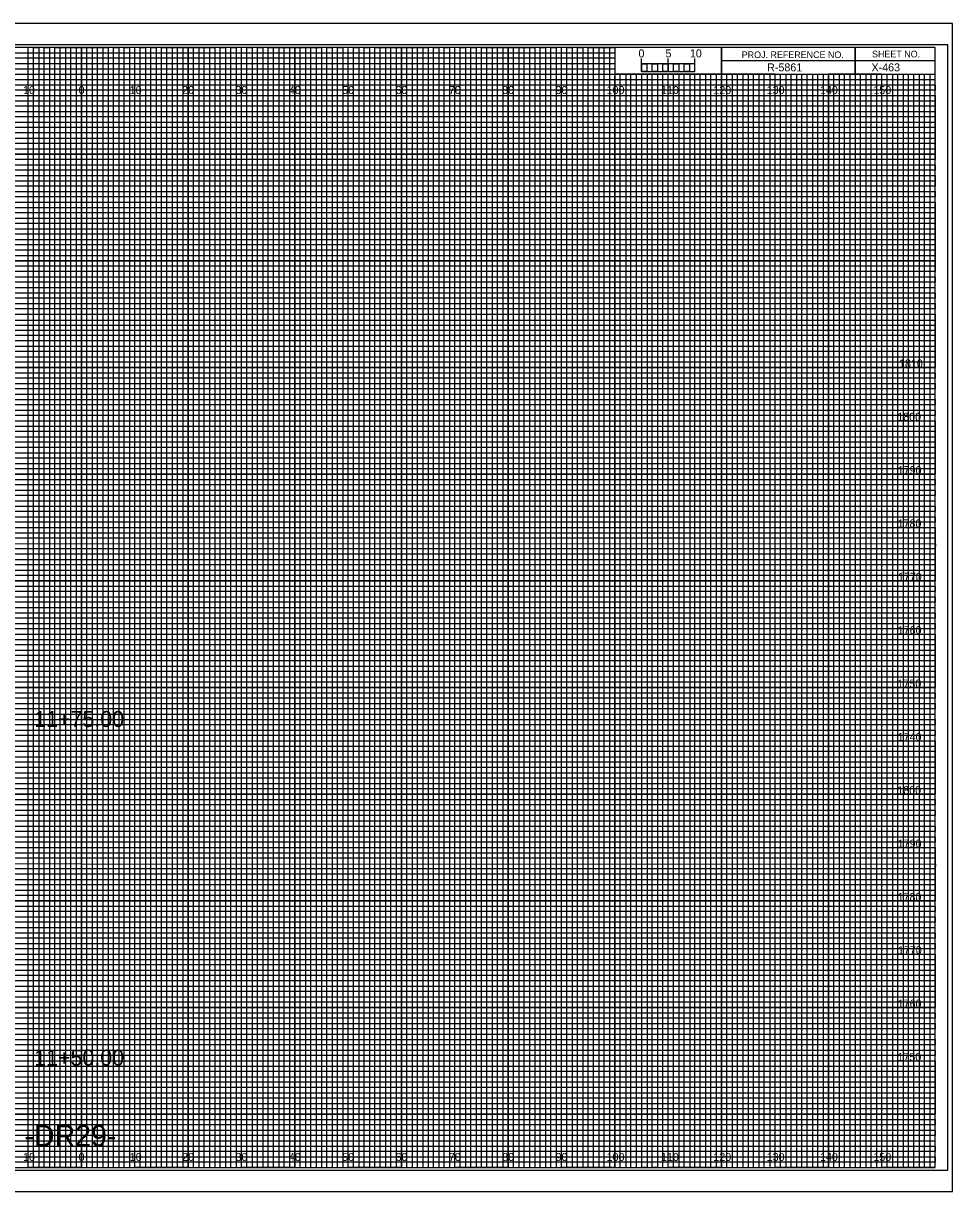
# Model space of a CAD drawing. Extents: x -13 to 323, y -5 to 874.
# Drawn here: x 149.1 to 323.3, y 435.5 to 654.5 of the extents above; entities that cross this region are included whole.
import ezdxf

# ---------------------------------------------------------------- set-up
doc = ezdxf.new("R2010")
doc.units = 0
for name, color, linetype in [('Prop Horizontal Alignment', 7, 'Continuous'), ('Prop XS Alignment Label', 7, 'Continuous'), ('Prop XS Bar Scale Labels', 7, 'Continuous'), ('Prop XS DDE', 7, 'Continuous'), ('Prop XS DDE Elevations', 7, 'Continuous'), ('Prop XS DDE Slope Text', 7, 'Continuous'), ('Prop XS Gore Control Minimum', 7, 'Continuous'), ('Prop XS Project Number', 7, 'Continuous'), ('Prop XS Sheet Number', 7, 'Continuous'), ('Prop XS Shoulder Borrow Shape', 7, 'Continuous'), ('Raster_Level_0', 7, 'Continuous'), ('Scratch_Level_3', 7, 'Continuous'), ('Sheet Cross Section Scale CELL', 7, 'Continuous'), ('Sheet Cutting Line CELL', 7, 'Continuous'), ('Sheet DOT Grid CELL', 7, 'Continuous'), ('Sheet Plot Border Inside CELL', 7, 'Continuous'), ('Sheet Plot Border Outside CELL', 7, 'Continuous')]:
    doc.layers.add(name, color=color, linetype=linetype)

msp = doc.modelspace()

# ---------------------------------------------------------------- linework, layer by layer
at = {"layer": 'Prop XS DDE'}
for p, q in [((0, 649), (260, 649)), ((260, 649), (260, 647.98)), ((260, 647.98), (0, 647.98)), ((0, 647), (260, 647)), ((260, 647), (260, 645.89)), ((260, 645.89), (0, 645.89)), ((0, 644), (320, 644))]:
    msp.add_line(p, q, dxfattribs=at)
for points in [[(0, 643), (270, 643), (320, 643), (320, 642), (0, 642)], [(0, 641), (320, 641), (320, 639), (0, 639)], [(0, 638), (320, 638), (320, 637), (0, 636.98)], [(0, 636), (320, 636), (320, 634), (0, 634)], [(0, 633), (320, 633), (320, 632), (0, 632)], [(0, 631), (320, 631), (320, 629), (0, 629)], [(0, 628), (320, 628), (320, 627), (0, 627)], [(0, 626), (320, 626), (320, 624), (0, 624)], [(0, 623), (320, 623), (320, 622), (0, 622)], [(0, 621), (320, 621), (320, 619), (0, 619)], [(0, 618), (320, 618), (320, 617), (0, 617)], [(0, 616), (320, 616), (320, 613.95), (320, 613), (320, 612), (0, 612)], [(0, 614), (320, 614), (320, 613), (0, 613)], [(0, 611), (320, 611), (320, 609), (0, 609.03)], [(0, 609.03), (320, 609), (320, 608), (0, 608)], [(0, 607), (320, 607), (320, 606), (0, 606)], [(0, 604), (320, 604), (320, 603), (0, 603)], [(0, 602), (320, 602), (320, 601), (0, 601)], [(-0.07, 598.89), (320, 598.89), (320, 597.88), (-0.07, 597.88)], [(0, 597), (320, 597), (320, 596), (0, 596)], [(0, 594), (320, 594), (320, 593), (0, 593)], [(0, 592), (320, 592), (320, 591), (0, 591)], [(0, 589), (320, 589), (320, 588), (0, 588)], [(0, 587), (320, 587), (320, 586), (0, 586)], [(0, 584), (320, 584), (320, 583), (0, 583)], [(0, 582), (320, 582), (320, 581), (0, 581)], [(0, 579), (320, 579), (319.99, 577.98), (0, 578)], [(0, 577), (320, 577), (320, 576), (0, 576)], [(0, 574), (320, 574), (320, 573), (0, 573)], [(0, 572), (320, 572), (320, 571), (0, 571)], [(0, 569), (320, 569), (320, 568), (0, 568)], [(0, 567), (320, 567), (320, 566), (0, 566)], [(0, 564), (320, 564), (320, 563), (0, 563)], [(0, 562), (320, 562), (320, 561), (0, 561)], [(0, 559), (320, 559), (320, 558), (0, 558)], [(0, 556.99), (320.07, 556.91), (320, 556), (0, 556)], [(0, 554), (320, 554), (320, 553), (0, 553)], [(0, 552), (320, 552), (320, 551), (0, 551)], [(0, 549), (320, 549), (320, 548), (0, 548)], [(0, 547), (320, 547), (320, 546), (0, 546)], [(0, 544), (320, 544), (320, 543), (0, 543)], [(0, 542), (320, 542), (320, 541), (0, 541)], [(0, 539), (320, 539), (320, 538), (0, 538)], [(0, 537), (320, 537), (320, 536), (0, 536)], [(0, 534), (320, 534), (320, 533), (0, 533)], [(0, 532), (320, 532), (320, 531), (0, 531)], [(0, 529), (320, 529), (320, 528), (0, 528)], [(0, 527), (320, 527), (320, 526), (0, 526)], [(0, 524), (320, 524), (320, 523), (0, 523)], [(0, 522), (320, 522), (320, 521), (0, 521)], [(0, 519), (320, 519), (319.99, 517.98), (0, 518)], [(0, 517), (320, 517), (320, 516), (0, 516)], [(0, 514), (320, 514), (320, 513), (0, 513)], [(0, 512), (320, 512), (320, 511), (0, 511)], [(0, 509), (320, 509), (320, 508), (0, 508)], [(0, 507), (320, 507), (320, 506), (0, 506)], [(0, 504), (320, 504), (320, 503), (0, 503)], [(0, 502), (320, 502), (320, 501), (0, 501)], [(0, 499), (320, 499), (320, 498), (0, 498)], [(0, 496.99), (320.07, 496.91), (320, 496), (0, 496)], [(0, 494), (320, 494), (320, 493), (0, 493)], [(0, 492), (320, 492), (320, 491), (0, 491)], [(0, 489), (320, 489), (320, 488), (0, 488)], [(0, 487), (320, 487), (320, 486), (0, 486)], [(0, 484), (320, 484), (320, 483), (0, 483)], [(0, 482), (320, 482), (320, 481), (0, 481)], [(0, 479), (320, 479), (320, 478), (0, 478)], [(0, 477), (320, 477), (320, 476), (0, 476)], [(0, 474), (320, 474), (320, 473), (0, 473)], [(0, 472), (320, 472), (320, 471), (0, 471)], [(0, 469), (320, 469), (320, 468), (0, 468)], [(0, 467), (320, 467), (320, 466), (0, 466)], [(0, 464), (320, 464), (320, 463), (0, 463)], [(0, 462), (320, 462), (320, 461), (0, 461)], [(0, 459), (320, 459), (320, 458), (0, 458)], [(0, 457), (320, 457), (320, 456), (0, 456)], [(0, 454), (320, 454), (320, 453), (0, 453)], [(0, 452), (320, 452), (320, 451), (0, 451)], [(0, 449), (320, 449), (320, 448), (0, 448)], [(0, 447), (320, 447), (320, 446), (0, 446)], [(0, 444), (320, 444), (320, 443), (0, 443)], [(0, 442), (320, 442), (320, 441), (0, 441)]]:
    msp.add_lwpolyline(points, dxfattribs=at)
at = {"layer": 'Prop XS DDE Elevations'}
for p, q in [((267, 645), (266.01, 645)), ((266.01, 645), (266.01, 440)), ((267, 440), (267, 645)), ((269, 645), (268, 645)), ((268, 645), (268, 440)), ((269, 440), (269, 645)), ((266.01, 440), (265, 440)), ((268, 440), (267, 440))]:
    msp.add_line(p, q, dxfattribs=at)
for points in [[(150, 440), (151, 440), (151, 650), (152, 650), (152, 440)], [(152, 440), (153, 440), (153, 650), (154, 650), (154, 440)], [(155, 440), (156, 440), (156, 650), (157, 650), (157, 440)], [(157, 440), (158, 440), (158, 650), (159, 650), (159, 440)], [(160, 440), (161, 440), (161, 650), (162, 650), (162, 440)], [(162, 440), (163, 440), (163, 650), (164, 650), (164, 440)], [(165, 440), (166, 440), (166, 650), (167, 650), (167, 440)], [(167, 440), (168, 440), (168, 650), (169, 650), (169, 440)], [(170, 440), (171, 440), (171, 650), (172, 650), (172, 440)], [(172, 440), (173, 440), (173, 650), (174, 650), (174, 440)], [(175, 440), (176, 440), (176, 650), (177, 650), (177, 440)], [(177, 440), (178, 440), (178, 650), (179, 650), (179, 440)], [(180, 440), (181, 440), (181, 650), (182, 650), (182, 440)], [(182, 440), (183, 440), (183, 650), (184, 650), (184, 440)], [(185, 440), (186, 440), (186, 650), (187, 650), (187, 440)], [(187, 440), (188, 440), (188, 650), (189, 650), (189, 440)], [(190, 440), (191, 440), (191, 650), (192, 650), (192, 440)], [(192, 440), (193, 440), (193, 650), (194, 650), (194, 440)], [(195, 440), (196, 440), (196, 650), (197, 650), (197, 440)], [(197, 440), (198, 440), (198, 650), (199, 650), (199, 440)], [(200, 440), (201, 440), (201, 650), (202, 650), (202, 440)], [(202, 440), (203, 440), (203, 650), (204, 650), (204, 440)], [(205, 440), (206, 440), (206, 650), (207, 650), (207, 440)], [(207, 440), (208, 440), (208, 650), (209, 650), (209, 440)], [(210, 440), (211, 440), (211, 650), (212, 650), (212, 440)], [(212, 440), (213, 440), (213, 650), (214, 650), (214, 440)], [(215, 440), (216, 440), (216, 650), (217, 650), (217, 440)], [(217, 440), (218, 440), (218, 650), (219, 650), (219, 440)], [(220, 440), (221, 440), (221, 650), (222, 650), (222, 440)], [(222, 440), (223, 440), (223, 650), (224, 650), (224, 440)], [(225, 440), (226, 440), (226, 650), (227, 650), (227, 440)], [(227, 440), (228, 440), (228, 650), (229, 650), (229, 440)], [(230, 440), (231, 440), (231, 650), (232, 650), (232, 440)], [(232, 440), (233, 440), (233, 650), (234, 650), (234, 440)], [(235, 440), (236, 440), (236, 650), (237, 650), (237, 440)], [(237, 440), (238, 440), (238, 650), (239, 650), (239, 440)], [(240, 440), (241, 440), (241, 650), (242, 650), (242, 440)], [(242, 440), (243, 440), (243, 650), (244, 650), (244, 440)], [(245, 440), (246, 440), (246, 650), (247, 650), (247, 440)], [(247, 440), (248, 440), (248, 650), (249, 650), (249, 440)], [(250, 440), (251, 440), (251, 650), (252, 650), (252, 440)], [(252, 440), (253, 440), (253, 650), (254, 650), (254, 440)], [(255, 440), (256, 440), (256, 650), (257, 650), (257, 440)], [(257, 440), (258, 440), (258, 650), (259, 650), (259, 440)], [(260, 440), (261, 440), (261, 645), (262.02, 645), (262.02, 440)], [(262, 440), (263, 440), (263, 645), (263.99, 645), (263.99, 440)], [(270, 440), (270.98, 440), (270.98, 645), (272, 645), (272, 440)], [(272, 440), (273, 440), (273, 645), (274.05, 645), (274.05, 440)], [(275, 440), (276, 440), (276, 645), (277, 645), (277, 440)], [(277, 440), (278, 440), (278, 645), (279, 645), (279, 440)], [(280, 440), (281, 440), (281, 645), (282, 645), (282, 440)], [(282, 440), (283, 440), (283, 645), (284, 645), (284, 440)], [(285, 440), (286, 440), (286, 645), (287, 645), (287, 440)], [(287, 440), (288, 440), (288, 645), (289, 645), (289, 440)], [(290, 440), (291, 440), (291, 645), (292, 645), (292, 440)], [(292, 440), (293, 440), (293, 645), (294, 645), (294, 440)], [(295, 440), (296, 440), (296, 645), (297, 645), (297, 440)], [(297, 440), (298, 440), (298, 645), (299, 645), (299, 440)], [(300, 440), (301, 440), (301, 645), (302, 645), (302, 440)], [(302, 440), (303, 440), (303, 645), (304, 645), (304, 440)], [(305, 440), (306, 440), (306, 645), (307, 645), (307, 440)], [(307, 440), (308, 440), (308, 645), (309, 645), (309, 440)], [(310, 440), (311, 440), (311, 645), (312, 645), (312, 440)], [(312, 440), (313, 440), (313, 645), (314, 645), (314, 440)], [(315, 440), (316, 440), (316, 645), (317, 645), (317, 440)], [(317, 440), (318, 440), (318, 645), (319, 645), (319, 440)]]:
    msp.add_lwpolyline(points, dxfattribs=at)
at = {"layer": 'Prop XS DDE Slope Text'}
for p, q in [((305, 650), (305, 645)), ((305, 645), (305, 650)), ((280, 647.5), (280, 645)), ((320, 647.49), (280, 647.49)), ((280, 645), (320, 645))]:
    msp.add_line(p, q, dxfattribs=at)
for points in [[(320, 650), (0, 650), (0, 440), (320, 440)], [(280, 650), (260, 650), (260, 645.03), (280, 645.03)], [(320, 650), (280, 650), (280, 645), (320, 645)]]:
    msp.add_lwpolyline(points, close=True, dxfattribs=at)
at = {"layer": 'Prop XS Gore Control Minimum'}
for p, q in [((150, 650), (140, 650)), ((150, 440), (150, 650)), ((170, 650), (160, 650)), ((160, 650), (160, 440)), ((170, 440), (170, 650)), ((190, 650), (180, 650)), ((180, 650), (180, 440)), ((190, 440), (190, 650)), ((210, 650), (200, 650)), ((200, 650), (200, 440)), ((210, 440), (210, 650)), ((230, 650), (220, 650)), ((220, 650), (220, 440)), ((230, 440), (230, 650)), ((250, 650), (240, 650)), ((240, 650), (240, 440)), ((250, 440), (250, 650)), ((260, 650), (260, 440)), ((270, 440), (270, 645)), ((290, 645), (280, 645)), ((280, 645), (280, 440)), ((290, 440), (290, 645)), ((310, 645), (300, 645)), ((300, 645), (300, 440)), ((310, 440), (310, 645)), ((160, 440), (150, 440)), ((180, 440), (170, 440)), ((200, 440), (190, 440)), ((220, 440), (210, 440)), ((240, 440), (230, 440)), ((260, 440), (250, 440)), ((280, 440), (270, 440)), ((300, 440), (290, 440)), ((320, 440), (310, 440)), ((320, 440), (320, 440))]:
    msp.add_line(p, q, dxfattribs=at)
for points in [[(0, 640), (320, 640), (320, 630), (0, 630)], [(0, 620), (320, 620), (320, 610), (0, 610)], [(0, 600), (320, 600), (320, 590), (0, 590)], [(0, 580), (320, 580), (320, 570), (0, 570)], [(0, 560), (320, 560), (320, 550), (0, 550)], [(0, 540), (320, 540), (320, 530), (0, 530)], [(0, 520), (320, 520), (320, 510), (0, 510)], [(0, 500), (320, 500), (320, 490), (0, 490)], [(0, 480), (320, 480), (320, 470), (0, 470)], [(0, 460), (320, 460), (320, 450), (0, 450)]]:
    msp.add_lwpolyline(points, dxfattribs=at)
at = {"layer": 'Prop XS Shoulder Borrow Shape'}
for points in [[(145, 440), (155, 440), (155, 650), (165, 650), (165, 440), (175, 440), (175, 650), (185, 650), (185, 440), (195, 440), (195, 650), (205, 650), (205, 440), (215, 440), (215, 650), (225, 650), (225, 440), (235, 440), (235, 650), (245, 650), (245, 440), (255, 440), (255, 650), (259.93, 650), (260, 650), (260, 645), (264.99, 645), (264.99, 440), (275, 440), (275, 645), (285, 645), (285, 440), (295, 440), (295, 645), (305, 645), (305, 440), (315, 440), (315, 645)], [(0, 645), (275, 645)], [(0, 625), (320, 625), (320, 635), (0, 635)], [(0, 605), (320, 605), (320, 615), (0, 615)], [(0, 585), (320, 585), (320, 595), (0, 595)], [(0, 565), (320, 565), (320, 575), (0, 575)], [(0, 545), (320, 545), (320, 555), (0, 555)], [(0, 525), (320, 525), (320, 535), (0, 535)], [(0, 505), (320, 505), (320, 515), (0, 515)], [(0, 485), (320, 485), (320, 495), (0, 495)], [(0, 465), (320, 465), (320, 475), (0, 475)], [(0, 445), (320, 445), (320, 455), (0, 455)]]:
    msp.add_lwpolyline(points, dxfattribs=at)
at = {"layer": 'Sheet Cross Section Scale CELL'}
for p, q in [((265, 645.49), (265, 647.9)), ((265, 646.9), (265, 647.9)), ((270, 645.49), (270, 647.9)), ((275, 645.49), (275, 647.9)), ((275, 646.9), (275, 647.9))]:
    msp.add_line(p, q, dxfattribs=at)
for points in [[(275, 646.9), (265, 646.9), (265, 645.49), (275, 645.49)], [(265, 646.9), (266, 646.9), (266, 645.49), (265, 645.49)], [(267, 646.9), (268, 646.9), (268, 645.49), (267, 645.49)], [(269, 646.9), (270, 646.9), (270, 645.49), (269, 645.49)], [(271, 646.9), (272, 646.9), (272, 645.49), (271, 645.49)], [(273, 646.9), (274, 646.9), (274, 645.49), (273, 645.49)]]:
    msp.add_lwpolyline(points, close=True, dxfattribs=at)
at = {"layer": 'Sheet Cutting Line CELL'}
for p, q in [((323.3, 654.5), (-13.4, 654.5)), ((-13.4, 435.5), (323.3, 435.5))]:
    msp.add_line(p, q, dxfattribs=at)
at = {"layer": 'Sheet DOT Grid CELL'}
for p, q in [((150, 440), (150, 650)), ((160, 440), (160, 650)), ((170, 440), (170, 650)), ((180, 440), (180, 650)), ((190, 440), (190, 650)), ((200, 440), (200, 650)), ((210, 440), (210, 650)), ((220, 440), (220, 650)), ((230, 440), (230, 650)), ((240, 440), (240, 650)), ((250, 440), (250, 650)), ((260, 440), (260, 644.69)), ((270, 440), (270, 644.69)), ((280, 440), (280, 644.69)), ((290, 440), (290, 644.69)), ((300, 440), (300, 644.69)), ((310, 440), (310, 644.69)), ((0, 640), (320, 640)), ((0, 630), (320, 630)), ((0, 620), (320, 620)), ((0, 610), (320, 610)), ((0, 600), (320, 600)), ((0, 590), (320, 590)), ((0, 580), (320, 580)), ((0, 570), (320, 570)), ((0, 560), (320, 560)), ((0, 550), (320, 550)), ((0, 540), (320, 540)), ((0, 530), (320, 530)), ((0, 520), (320, 520)), ((0, 510), (320, 510)), ((0, 500), (320, 500)), ((0, 490), (320, 490)), ((0, 480), (320, 480)), ((0, 470), (320, 470)), ((0, 460), (320, 460)), ((0, 450), (320, 450))]:
    msp.add_line(p, q, dxfattribs=at)
at = {"layer": 'Sheet Plot Border Inside CELL'}
msp.add_lwpolyline([(-10.8, 439.5), (322.4, 439.5), (322.4, 650.5), (-10.8, 650.5)], close=True, dxfattribs=at)
at = {"layer": 'Sheet Plot Border Outside CELL'}
msp.add_lwpolyline([(-13.4, 435.5), (323.3, 435.5), (323.3, 654.5), (-13.4, 654.5)], close=True, dxfattribs=at)

# ---------------------------------------------------------------- texts
at = {"layer": 'Prop Horizontal Alignment'}
for s, p in [('11+75.00', (151.13, 522.6)), ('11+50.00', (151.13, 459.12))]:
    msp.add_text(s, height=3, dxfattribs=at).set_placement(p)
at = {"layer": 'Prop XS Alignment Label'}
msp.add_text('-DR29-', height=4, dxfattribs=at).set_placement((149.3, 444))
at = {"layer": 'Prop XS Bar Scale Labels'}
for s, p in [('5', (269.47, 648.12)), ('10', (274.04, 648.12))]:
    msp.add_text(s, height=1.5, dxfattribs=at).set_placement(p)
at = {"layer": 'Prop XS DDE Slope Text'}
for s, p in [('PROJ. REFERENCE NO.', (283.77, 647.99)), ('SHEET NO.', (308.19, 648.12))]:
    msp.add_text(s, height=1.25, dxfattribs=at).set_placement(p)
at = {"layer": 'Prop XS Project Number'}
msp.add_text('R-5861', height=1.5, dxfattribs=at).set_placement((288.53, 645.5))
at = {"layer": 'Prop XS Sheet Number'}
msp.add_text('X-463', height=1.5, dxfattribs=at).set_placement((308.09, 645.5))
at = {"layer": 'Raster_Level_0'}
for s, p in [('10', (149.04, 641.25)), ('0', (159.45, 641.25)), ('0', (159.45, 641.25)), ('10', (169.04, 641.25)), ('20', (178.86, 641.25)), ('30', (188.86, 641.25)), ('40', (198.86, 641.25)), ('50', (208.86, 641.25)), ('60', (218.86, 641.25)), ('70', (228.86, 641.25)), ('80', (238.86, 641.25)), ('90', (248.86, 641.25)), ('100', (258.44, 641.25)), ('110', (268.62, 641.25)), ('120', (278.44, 641.25)), ('130', (288.44, 641.25)), ('140', (298.44, 641.25)), ('150', (308.44, 641.25)), ('10', (149.04, 441.25)), ('0', (159.45, 441.25)), ('0', (159.45, 441.25)), ('10', (169.04, 441.25)), ('20', (178.86, 441.25)), ('30', (188.86, 441.25)), ('40', (198.86, 441.25)), ('50', (208.86, 441.25)), ('60', (218.86, 441.25)), ('70', (228.86, 441.25)), ('80', (238.86, 441.25)), ('90', (248.86, 441.25)), ('100', (258.44, 441.25)), ('110', (268.62, 441.25)), ('120', (278.44, 441.25)), ('130', (288.44, 441.25)), ('140', (298.44, 441.25)), ('150', (308.44, 441.25))]:
    msp.add_text(s, height=1.5, dxfattribs=at).set_placement(p)
at = {"layer": 'Scratch_Level_3'}
for s, p in [('1810', (313.25, 590)), ('1800', (312.92, 580)), ('1790', (313, 570)), ('1780', (312.98, 560)), ('1770', (313.04, 550)), ('1760', (313, 540)), ('1750', (312.96, 530)), ('1740', (313, 520)), ('1800', (312.92, 510)), ('1790', (313, 500)), ('1780', (312.98, 490)), ('1770', (313.04, 480)), ('1760', (313, 470)), ('1750', (312.96, 460))]:
    msp.add_text(s, height=1.5, dxfattribs=at).set_placement(p)
at = {"layer": 'Sheet Cross Section Scale CELL'}
msp.add_text('0', height=1.5, dxfattribs=at).set_placement((264.41, 648.12))

doc.saveas('drawing.dxf')
